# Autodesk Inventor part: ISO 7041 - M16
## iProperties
Created: 2001-08
Part Number: ISO 7041 - M16
Catalog Web Link: file:///D:/Program%20Files/Autodesk/Inventor%205/Content/Iso/index.htm?doNavigateId=91C8CC99-3893-4F49-8D02-DF1401D4CEFB|1F9905F51971489DBD3F91838FFFA500|true
Description: Hex Nut with Torque Part
Document SubType Name: Standard Catalog Part
Standard: ISO 7041 - M16
Designer: Martin Budgell
Control State: 0
Master: False
Checked Out: False
Length Units: 11269
Angle Units: 11279
Time Units: 11290
Mass Units: 11283
Shininess: 3
Angle Display Precision: 2
Document Length Units: 11269
Document Angle Units: 11279
Document Time Units: 11290
Document Mass Units: 11283
Document Length Units Precision: 3
Document Angle Units Precision: 2
Compacted: True
CLASSIFICATION: 31161727 un/spsc
MANUFACTURER: ISO Standard System
Density: 0.0
Volumn: 0.0
Area: 0.0
PropertySet Name: Model Information
Author: Martin Budgell
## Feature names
1. Base1
